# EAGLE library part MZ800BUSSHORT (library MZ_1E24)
44-bit BUS for MZ800
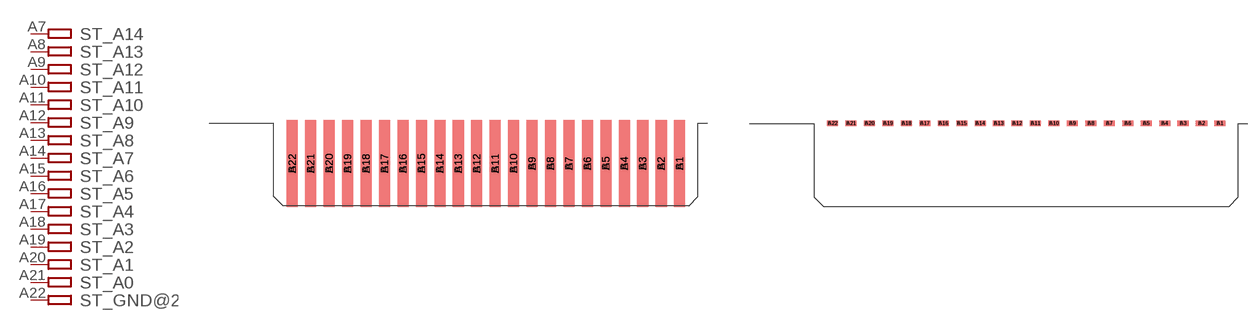
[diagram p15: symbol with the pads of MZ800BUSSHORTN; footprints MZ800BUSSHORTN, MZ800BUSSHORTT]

Designator prefix ST; gates _GND@2=ATPIN _A0=ATPIN _A1=ATPIN _A2=ATPIN _A3=ATPIN _A4=ATPIN _A5=ATPIN _A6=ATPIN _A7=ATPIN _A8=ATPIN _A9=ATPIN _A10=ATPIN _A11=ATPIN _A12=ATPIN _A13=ATPIN _A14=ATPIN _A15=ATPIN _GND@1=ATPIN _D0=ATPIN _D1=ATPIN _D2=ATPIN _+5V@1=ATPIN _GND@4=ATPIN _NC@5=ATPIN _EXWAIT/=ATPIN _INT/=ATPIN _EXRESET/=ATPIN _RESET=ATPIN _NC@4=ATPIN _IEI=ATPIN _HALT/=ATPIN _GND@3=ATPIN _MREQ/=ATPIN _IORQ/=ATPIN _RD/=ATPIN _WR/=ATPIN _M1/=ATPIN _BUS0=ATPIN _D7=ATPIN _D6=ATPIN _D5=ATPIN _D4=ATPIN _D3=ATPIN _+5V@2=ATPIN

## MZ800BUSSHORTN  [MZ800BUSSHORTN]
A1  _+5V@1:P
A2  _D2:P
A3  _D1:P
A4  _D0:P
A5  _GND@1:P
A6  _A15:P
A7  _A14:P
A8  _A13:P
A9  _A12:P
A10  _A11:P
A11  _A10:P
A12  _A9:P
A13  _A8:P
A14  _A7:P
A15  _A6:P
A16  _A5:P
A17  _A4:P
A18  _A3:P
A19  _A2:P
A20  _A1:P
A21  _A0:P
A22  _GND@2:P
B1  _+5V@2:P
B2  _D3:P
B3  _D4:P
B4  _D5:P
B5  _D6:P
B6  _D7:P
B7  _BUS0:P
B8  _M1/:P
B9  _WR/:P
B10  _RD/:P
B11  _IORQ/:P
B12  _MREQ/:P
B13  _GND@3:P
B14  _HALT/:P
B15  _IEI:P
B16  _NC@4:P
B17  _RESET:P
B18  _EXRESET/:P
B19  _INT/:P
B20  _EXWAIT/:P
B21  _NC@5:P
B22  _GND@4:P

## MZ800BUSSHORTT  [MZ800BUSSHORTT]
Pads as for MZ800BUSSHORTN

## Footprint MZ800BUSSHORTN (pad centres in mm)
50-bit CARD MZ800
smd 1.524 x 11.938: A1 64.77,-4.318; A2 62.23,-4.318; A3 59.69,-4.318; A4 57.15,-4.318; A5 54.61,-4.318; A6 52.07,-4.318; A7 49.53,-4.318; A8 46.99,-4.318; A9 44.45,-4.318; A10 41.91,-4.318; A11 39.37,-4.318; A12 36.83,-4.318; A13 34.29,-4.318; A14 31.75,-4.318; A15 29.21,-4.318; A16 26.67,-4.318; A17 24.13,-4.318; A18 21.59,-4.318; A19 19.05,-4.318; A20 16.51,-4.318; A21 13.97,-4.318; A22 11.43,-4.318
smd 1.524 x 11.938 bottom: B1 64.77,-4.318; B2 62.23,-4.318; B3 59.69,-4.318; B4 57.15,-4.318; B5 54.61,-4.318; B6 52.07,-4.318; B7 49.53,-4.318; B8 46.99,-4.318; B9 44.45,-4.318; B10 41.91,-4.318; B11 39.37,-4.318; B12 36.83,-4.318; B13 34.29,-4.318; B14 31.75,-4.318; B15 29.21,-4.318; B16 26.67,-4.318; B17 24.13,-4.318; B18 21.59,-4.318; B19 19.05,-4.318; B20 16.51,-4.318; B21 13.97,-4.318; B22 11.43,-4.318

## Footprint MZ800BUSSHORTT (pad centres in mm)
50-bit CARD MZ800
smd 1.524 x 0.762: A1 64.77,1.27; A2 62.23,1.27; A3 59.69,1.27; A4 57.15,1.27; A5 54.61,1.27; A6 52.07,1.27; A7 49.53,1.27; A8 46.99,1.27; A9 44.45,1.27; A10 41.91,1.27; A11 39.37,1.27; A12 36.83,1.27; A13 34.29,1.27; A14 31.75,1.27; A15 29.21,1.27; A16 26.67,1.27; A17 24.13,1.27; A18 21.59,1.27; A19 19.05,1.27; A20 16.51,1.27; A21 13.97,1.27; A22 11.43,1.27
smd 1.524 x 0.762 bottom: B1 64.77,1.27; B2 62.23,1.27; B3 59.69,1.27; B4 57.15,1.27; B5 54.61,1.27; B6 52.07,1.27; B7 49.53,1.27; B8 46.99,1.27; B9 44.45,1.27; B10 41.91,1.27; B11 39.37,1.27; B12 36.83,1.27; B13 34.29,1.27; B14 31.75,1.27; B15 29.21,1.27; B16 26.67,1.27; B17 24.13,1.27; B18 21.59,1.27; B19 19.05,1.27; B20 16.51,1.27; B21 13.97,1.27; B22 11.43,1.27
